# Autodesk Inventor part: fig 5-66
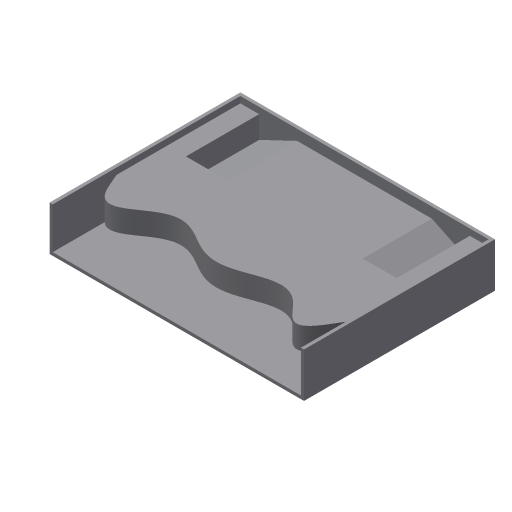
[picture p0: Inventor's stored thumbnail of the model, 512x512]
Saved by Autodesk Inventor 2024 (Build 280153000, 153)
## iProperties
Created: 2004-05
Part Number: fig 5-66
Document SubType Name: Modeling
Designer: CADCIM Technologies
Manufacturer: Standard
Standards Organization: Custom
Density: 1 g/cm^3
Material: Generic
Appearance: Default
Author: CADCIM Technologies
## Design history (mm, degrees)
sketch "Sketch1"
  geometry: L1 (-40, -30)-(40, -30); L2 (40, -30)-(40, 30); L3 (40, 30)-(-40, 30); L4 (-40, 30)-(-40, -30); 1 further point
  constraints: 8 end point, 2 parallel, 1 horizontal, 1 perpendicular, 1 other
  dimensions: "d0" = 80 distance of L1.start L1.end; "d1" = 60 distance of L3.end L1.start; "d2" = 30 distance from line of point (0, 0) L1; "d3" = 40 distance from line of point (0, 0) L4
extrude "Extrusion1" new body sketch "Sketch1" distance "d4" = 14; taper "d5" = 0 deg
shell "Shell1" dims "d6" = 1
workplane "Work Plane1"
sketch "Sketch2"
  geometry: L1 (78, -13)-(78, -11.813); L2 (0, -11.813)-(0, -13); L3 (0, -13)-(78, -13); L4 (0, -11.813)-(17.826, -3.295); L5 (17.826, -3.295)-(60.174, -3.295); L6 (60.174, -3.295)-(78, -11.813); L7 (79, -13.795)-(78, -13.795); L8 (78, 0)-(78, -13) reference; L9 (0, -13)-(0, 0) reference; L10 (78, -13)-(0, -13) reference
  constraints: 14 end point, 3 collinear, 2 equal length, 2 vertical, 1 horizontal alignment, 1 parallel, 1 point on line
extrude "Extrusion2" join sketch "Sketch2" stored distance "d8" = 14; taper "d9" = 0 deg
workplane "Work Plane2"
sketch "Sketch3"
  geometry: 7 further points
  constraints: 7 other
extrude "Extrusion7" join sketch "Sketch3" distance "d27" = 7; taper "d28" = 0 deg
body "Solid1"
other parameters: "d7" = 23, "d18" = 4, "d29" = 7
